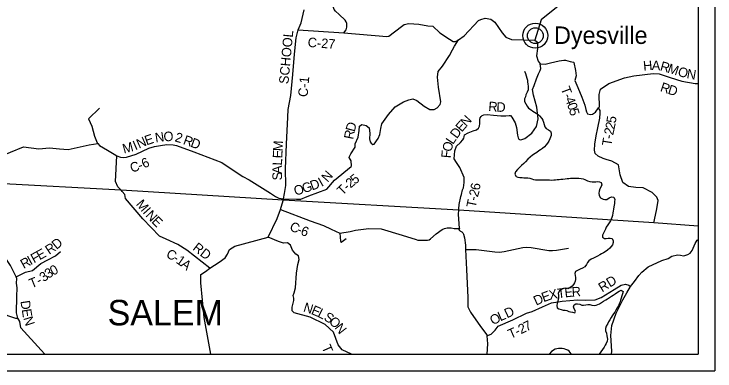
# Model space of a CAD drawing. Extents: x -84548 to 2262448, y -162180 to 525962.
# Drawn here: x -22558 to -515, y 130056 to 141282 of the extents above; entities that cross this region are included whole.
import ezdxf

# ---------------------------------------------------------------- set-up
doc = ezdxf.new("R2010")
doc.units = 0
for name, color, linetype in [('GM_X_Adjacent_County_Text', 7, 'Continuous'), ('GM_X_Corporation_Text', 7, 'Continuous'), ('GM_X_County', 7, 'Continuous'), ('GM_X_County_Road', 7, 'Continuous'), ('GM_X_Hydro', 7, 'Continuous'), ('GM_X_Interstate_Location', 7, 'Continuous'), ('GM_X_Major_River', 7, 'Continuous'), ('GM_X_Minor_Lake', 7, 'Continuous'), ('GM_X_Minor_River_Text', 7, 'Continuous'), ('GM_X_Township_Road', 7, 'Continuous'), ('GM_X_Township_Road_Text', 7, 'Continuous'), ('GM_X_Township_ROW', 7, 'Continuous')]:
    doc.layers.add(name, color=color, linetype=linetype)

msp = doc.modelspace()

# ---------------------------------------------------------------- linework, layer by layer
at = {"layer": 'GM_X_County'}
for p, q in [((-515, 167016), (-515, 130056)), ((-1043, 166488), (-1043, 130584)), ((-1043, 166488), (-1043, 130584)), ((-36947, 130584), (-1043, 130584)), ((-36947, 130584), (-1043, 130584)), ((-37475, 130056), (-515, 130056))]:
    msp.add_line(p, q, dxfattribs=at)
at = {"layer": 'GM_X_Hydro'}
for p, q in [((-19190, 135747), (-23639, 135977)), ((-14093, 135426), (-19190, 135747)), ((-8572, 135110), (-14093, 135426)), ((-2434, 134710), (-8572, 135110)), ((-1043, 134612), (-2434, 134710))]:
    msp.add_line(p, q, dxfattribs=at)
at = {"layer": 'GM_X_Interstate_Location'}
for points in [[(-6508, 139480), (-6475, 139408), (-6451, 139342), (-6431, 139270), (-6414, 139200), (-6406, 139142), (-6402, 139082), (-6392, 139004), (-6391, 138952), (-6393, 138896), (-6419, 138824), (-6458, 138739), (-6476, 138681), (-6502, 138617), (-6500, 138533), (-6465, 138453), (-6417, 138381), (-6375, 138321), (-6298, 138266), (-6238, 138232), (-6188, 138200), (-6134, 138162), (-6078, 138126), (-6028, 138081), (-5959, 137999), (-5923, 137939), (-5907, 137883), (-5886, 137803), (-5862, 137733), (-5824, 137681), (-5754, 137645), (-5691, 137600), (-5663, 137532), (-5669, 137463), (-5687, 137413), (-5708, 137353), (-5740, 137281), (-5784, 137221), (-5828, 137166), (-5875, 137100), (-5935, 137050), (-5999, 137007), (-6051, 136975), (-6116, 136931), (-6168, 136896), (-6248, 136844), (-6324, 136784), (-6400, 136715), (-6469, 136637), (-6525, 136582), (-6599, 136516), (-6662, 136450), (-6724, 136389), (-6792, 136323), (-6805, 136243), (-6769, 136173), (-6711, 136147), (-6655, 136143), (-6575, 136136), (-6521, 136134), (-6457, 136132), (-6405, 136128), (-6339, 136121), (-6275, 136101), (-6225, 136081), (-6155, 136070), (-6085, 136070), (-6031, 136068), (-5977, 136068), (-5917, 136067), (-5843, 136067), (-5783, 136063), (-5719, 136064), (-5659, 136062), (-5585, 136064), (-5533, 136068), (-5473, 136075), (-5419, 136081), (-5367, 136085), (-5299, 136089), (-5223, 136098), (-5165, 136106), (-5109, 136112), (-5055, 136117), (-4975, 136119), (-4869, 136119), (-4791, 136118), (-4727, 136110), (-4659, 136098), (-4603, 136081), (-4519, 136033), (-4445, 136015), (-4374, 136004), (-4310, 136004), (-4257, 136006), (-4195, 136010), (-4145, 136005), (-4092, 135985), (-4074, 135911), (-4098, 135853), (-4134, 135780)], [(-4134, 135780), (-4157, 135710), (-4167, 135652), (-4159, 135572), (-4110, 135498), (-4032, 135458), (-3980, 135447), (-3912, 135453), (-3842, 135497), (-3766, 135532), (-3696, 135526), (-3668, 135448), (-3670, 135388), (-3676, 135322), (-3681, 135272), (-3691, 135216), (-3701, 135148), (-3713, 135087), (-3724, 135029), (-3740, 134943), (-3758, 134883), (-3777, 134833), (-3805, 134775), (-3843, 134720), (-3885, 134652), (-3932, 134580), (-3962, 134512), (-3990, 134451), (-4023, 134393), (-4055, 134331), (-4049, 134259), (-3991, 134225), (-3937, 134227), (-3873, 134234), (-3811, 134236), (-3745, 134218), (-3714, 134148), (-3716, 134094), (-3742, 134024), (-3782, 133970), (-3825, 133918), (-3897, 133855), (-3969, 133805), (-4025, 133770), (-4081, 133742), (-4138, 133708), (-4210, 133669), (-4272, 133635), (-4336, 133607), (-4404, 133572), (-4478, 133520), (-4519, 133468), (-4559, 133402), (-4611, 133335), (-4676, 133287), (-4756, 133259), (-4822, 133226), (-4896, 133180), (-4918, 133118), (-4911, 133060), (-4901, 132998), (-4901, 132935), (-4909, 132877), (-4928, 132823), (-4962, 132771), (-5008, 132719), (-5084, 132672), (-5140, 132640), (-5208, 132658), (-5274, 132645), (-5342, 132621), (-5407, 132579), (-5443, 132508), (-5435, 132432), (-5436, 132356), (-5444, 132304), (-5458, 132248), (-5474, 132178), (-5485, 132112), (-5479, 132046), (-5421, 132012), (-5351, 131984), (-5287, 131973), (-5227, 131965), (-5173, 131955), (-5106, 131929), (-5054, 131918), (-4992, 131908), (-4922, 131880), (-4903, 131938), (-4943, 132008), (-4959, 132072), (-4947, 132138), (-4886, 132167), (-4834, 132169), (-4768, 132161), (-4697, 132129), (-4647, 132122), (-4579, 132134), (-4511, 132150), (-4447, 132145)], [(-4447, 132145), (-4385, 132121), (-4317, 132115), (-4251, 132125), (-4200, 132146), (-4148, 132172), (-4082, 132206), (-4024, 132247), (-3950, 132293), (-3898, 132327), (-3773, 132412), (-3721, 132444), (-3653, 132487), (-3581, 132533), (-3529, 132569), (-3464, 132598), (-3401, 132556), (-3423, 132484), (-3443, 132417), (-3466, 132347), (-3482, 132283), (-3500, 132233), (-3526, 132169), (-3553, 132101), (-3587, 132042), (-3631, 131970), (-3664, 131908), (-3702, 131854), (-3750, 131787), (-3780, 131735), (-3825, 131663), (-3859, 131601), (-3889, 131550), (-3935, 131464), (-3954, 131394), (-3954, 131314), (-3926, 131242), (-3911, 131162), (-3901, 131104), (-3897, 131054), (-3904, 130998), (-3934, 130919), (-3964, 130867), (-4000, 130801), (-4053, 130733), (-4103, 130662), (-4157, 130584), (-4157, 130584)]]:
    msp.add_lwpolyline(points, dxfattribs=at)
at = {"layer": 'GM_X_Major_River'}
for radius in [393, 249]:
    msp.add_circle((-6165, 140602), radius, dxfattribs=at)
at = {"layer": 'GM_X_Minor_Lake'}
for points in [[(-13411, 135512), (-13287, 135569), (-12725, 135775), (-12478, 136055), (-11954, 136488), (-11943, 136506), (-11959, 136665), (-12021, 136766), (-12023, 136780), (-11968, 136886), (-11828, 137092), (-11826, 137196), (-11733, 137413), (-11703, 137618), (-11692, 137758), (-11619, 137804), (-11487, 137780), (-11393, 137698), (-11371, 137520), (-11380, 137362), (-11361, 137264), (-11328, 137219), (-11276, 137176), (-11230, 137184), (-11103, 137372), (-11050, 137496), (-11026, 137682), (-10990, 137827), (-10784, 138125), (-10573, 138366), (-10314, 138519), (-10145, 138583), (-10014, 138615), (-9890, 138564), (-9659, 138385), (-9479, 138282), (-9347, 138282), (-9248, 138329), (-9159, 138435), (-9133, 138522), (-9213, 138977), (-9236, 139296), (-9218, 139472), (-9084, 139646), (-8862, 139981), (-8774, 140157), (-8701, 140276), (-8582, 140468)], [(-6176, 140455), (-6101, 140397), (-6094, 140198), (-6128, 139971), (-6080, 139797), (-6010, 139715), (-5855, 139700), (-5686, 139745), (-5411, 139814), (-5264, 139828), (-5217, 139829), (-5070, 139793), (-5069, 139793)], [(-5069, 139793), (-4967, 139768), (-4957, 139753), (-4899, 139503), (-4884, 139336), (-4918, 139194), (-4832, 138971), (-4698, 138670), (-4612, 138413), (-4574, 138276), (-4554, 138210), (-4537, 138165), (-4523, 138145), (-4427, 138120), (-4364, 138137), (-4272, 138191), (-4174, 138327), (-4147, 138364), (-4158, 138747), (-4114, 138915), (-3851, 139101), (-3358, 139272), (-3067, 139342), (-2456, 139411), (-2268, 139403), (-1928, 139290), (-1554, 139173), (-1141, 139093), (-1043, 139099)], [(-8490, 135602), (-8457, 135748), (-8424, 135817), (-8401, 135980), (-8402, 136140), (-8537, 136458), (-8646, 136616), (-8715, 136725), (-8695, 136977), (-8645, 137130), (-8519, 137244), (-8442, 137326), (-8411, 137375), (-8403, 137419), (-8390, 137485), (-8273, 137544), (-8114, 137606), (-8017, 137640), (-7948, 137697), (-7922, 137757), (-7909, 137837), (-7914, 137965), (-7904, 138022), (-7872, 138055), (-7831, 138095), (-7782, 138108), (-7677, 138118), (-7484, 138102), (-7245, 138083), (-7095, 138081), (-6988, 138095), (-6950, 138093), (-6900, 138034), (-6794, 137857), (-6755, 137718), (-6725, 137473), (-6702, 137391), (-6680, 137347), (-6664, 137338), (-6616, 137328), (-6491, 137368), (-6269, 137539), (-6124, 137742), (-6073, 137985), (-6116, 138350), (-6219, 138726), (-6257, 138907), (-6204, 139032), (-6125, 139247), (-6065, 139405), (-6010, 139501), (-5993, 139569), (-6010, 139715)], [(-20219, 137985), (-19873, 138321)], [(-4004, 136733), (-4029, 136742), (-4183, 136807), (-4278, 136891), (-4299, 137003), (-4291, 137194), (-4251, 137454), (-4194, 137700), (-4131, 138011), (-4121, 138165), (-4120, 138251), (-4174, 138327)], [(-23687, 136067), (-23688, 136069), (-23747, 136328), (-23755, 136415), (-23692, 136491), (-23452, 136613), (-22869, 136745), (-22790, 136882), (-22666, 136939), (-22260, 137101), (-21781, 137046), (-21437, 137078), (-21126, 137044), (-20859, 137025), (-20194, 137164), (-19924, 137208)], [(-8568, 135151), (-8555, 135293), (-8504, 135540), (-8490, 135602)], [(-14080, 135470), (-13674, 135455), (-13589, 135455), (-13535, 135462), (-13463, 135487), (-13411, 135512)], [(-21591, 130584), (-21705, 130712), (-22344, 131416), (-22376, 131611), (-22433, 131714), (-22481, 131889), (-22467, 132399), (-22464, 132666), (-22479, 132817), (-22473, 132969), (-22495, 133014), (-22669, 133371), (-23242, 134235), (-23385, 134405), (-23487, 134553), (-23516, 135246), (-23516, 135249)], [(-8553, 134541), (-8581, 134985), (-8572, 135110), (-8568, 135151)], [(-11950, 130584), (-12243, 130721), (-12369, 130883), (-12507, 131274), (-12774, 131516), (-13246, 131744), (-13748, 131885), (-13816, 131950), (-13807, 132062), (-13790, 132144), (-13756, 132268), (-13759, 132347), (-13780, 132431), (-13745, 132511), (-13709, 132671), (-13674, 133129), (-13636, 133401), (-13588, 133560), (-13615, 133674), (-13695, 133731), (-13796, 133853), (-13868, 134014), (-13954, 134084), (-14087, 134075), (-14243, 134123), (-14568, 134262)], [(-12317, 134385), (-12289, 134136), (-12284, 134117), (-12280, 134111), (-12275, 134108), (-12269, 134108), (-12261, 134112), (-12241, 134125), (-12114, 134221)], [(-22495, 133014), (-22193, 133161), (-21978, 133221), (-21716, 133431), (-21495, 133549), (-21251, 133678), (-21091, 133815)], [(-7688, 131164), (-7549, 131214), (-7425, 131334), (-7336, 131461), (-6874, 131659), (-6438, 131874), (-6262, 131924), (-5936, 132068), (-5653, 132204), (-5321, 132248), (-4841, 132298), (-4578, 132286), (-4286, 132292), (-4091, 132370), (-3690, 132619), (-3460, 132758), (-3333, 132784), (-3227, 132751), (-3171, 132712)], [(-26901, 131953), (-26395, 132177), (-25743, 132354), (-24553, 132256), (-23768, 132217), (-22768, 131796), (-22510, 131713), (-22433, 131714)], [(-5033, 130584), (-5037, 130593), (-5066, 130642), (-5100, 130679), (-5143, 130709), (-5200, 130733), (-5259, 130754), (-5317, 130767), (-5381, 130767), (-5440, 130764), (-5540, 130738), (-5651, 130672), (-5726, 130584)]]:
    msp.add_lwpolyline(points, dxfattribs=at)
at = {"layer": 'GM_X_Minor_River_Text'}
for points in [[(-5526, 142736), (-5525, 142728), (-5541, 142614), (-5546, 142563), (-5564, 142346), (-5507, 141959), (-5413, 141719), (-5382, 141651), (-5395, 141591), (-5403, 141577), (-5447, 141531), (-5978, 141095), (-6176, 140455)], [(-14096, 135415), (-14093, 135426), (-14080, 135470), (-14052, 135642), (-14013, 135893), (-14024, 136414), (-13989, 137191), (-13947, 138033), (-13934, 138278), (-13849, 138721), (-13790, 139383), (-13733, 140023), (-13681, 140535), (-13619, 140781), (-13531, 141003), (-13436, 141414)], [(-13619, 140781), (-12190, 140688), (-10831, 140571), (-10767, 140589), (-10375, 140888), (-10292, 140948), (-10139, 140979), (-9824, 140962), (-9547, 140912), (-9388, 140898), (-9167, 140689), (-8865, 140488), (-8749, 140419), (-8676, 140419), (-8610, 140447), (-8582, 140468), (-8405, 140599), (-7953, 141081), (-7873, 141108), (-7741, 141151), (-7566, 141121), (-7440, 141026), (-7212, 140692), (-7087, 140553), (-6918, 140481), (-6176, 140455)], [(-20219, 137985), (-20112, 137758), (-20026, 137444), (-19947, 137233), (-19924, 137208), (-19865, 137146), (-19621, 137000), (-19409, 136879), (-19329, 136820)], [(-19329, 136820), (-19213, 136781), (-19119, 136773), (-19022, 136784), (-18715, 136876), (-18316, 137059), (-18141, 137115), (-17956, 137151), (-17748, 137174), (-17555, 137172), (-17446, 137146), (-16906, 136948), (-16021, 136611), (-15694, 136390), (-15360, 136176), (-15166, 136068), (-14496, 135647), (-14330, 135538), (-14228, 135493), (-14080, 135470)], [(-19152, 135702), (-19190, 135747), (-19294, 135849), (-19369, 136014), (-19329, 136820)], [(-16400, 133291), (-17119, 133855), (-17408, 134037), (-17771, 134204), (-17979, 134296), (-18507, 134839), (-19055, 135482), (-19074, 135609), (-19152, 135702)], [(-16400, 133291), (-16103, 133482), (-15920, 133617), (-15843, 133725), (-15782, 133881), (-15617, 133982), (-14568, 134262), (-14287, 134849), (-14180, 135139), (-14096, 135415)], [(-14180, 135139), (-13246, 134781), (-12829, 134635), (-12585, 134517), (-12317, 134385), (-11989, 134447), (-11821, 134487), (-11399, 134533), (-11011, 134528), (-10352, 134332), (-9910, 134187), (-9855, 134175), (-9793, 134171), (-9553, 134171), (-9501, 134183), (-9461, 134210), (-9285, 134374), (-9095, 134503), (-9017, 134537), (-8941, 134557), (-8869, 134562), (-8810, 134559), (-8712, 134539), (-8553, 134541), (-8566, 134486), (-8480, 134437), (-8445, 134403), (-8421, 134363), (-8391, 134247), (-8365, 134013), (-8358, 133873), (-8330, 133246), (-8289, 132371), (-8282, 132074), (-8203, 131909), (-7884, 131456), (-7690, 131188), (-7688, 131164), (-7667, 130905), (-7688, 130584)], [(-3769, 130584), (-3753, 130682), (-3793, 131176), (-3759, 131487), (-3627, 131872), (-3413, 132289), (-3282, 132515), (-3171, 132712), (-3050, 132870), (-2906, 133063), (-2812, 133164), (-2618, 133330), (-2181, 133531), (-1986, 133595), (-1871, 133668), (-1688, 133710), (-1600, 133695), (-1507, 133682), (-1461, 133686), (-1367, 133721), (-1292, 133764), (-1237, 133846), (-1138, 134069), (-1073, 134167), (-1043, 134192)], [(-16365, 130584), (-16582, 131737), (-16678, 132827), (-16684, 133086), (-16539, 133183), (-16400, 133291)]]:
    msp.add_lwpolyline(points, dxfattribs=at)
at = {"layer": 'GM_X_Township_Road_Text'}
msp.add_lwpolyline([(-2434, 134710), (-2357, 135106), (-2308, 135348), (-2298, 135421), (-2340, 135520), (-2495, 135666), (-2776, 135816), (-3003, 135822), (-3231, 135853), (-3416, 135987), (-3492, 136226), (-3550, 136534), (-3761, 136653), (-3935, 136710), (-4004, 136733)], dxfattribs=at)
at = {"layer": 'GM_X_Township_ROW'}
for points in [[(-12190, 140688), (-12110, 140784), (-12090, 140870), (-12088, 140932), (-12094, 140988), (-12113, 141040), (-12146, 141084), (-12334, 141264), (-12450, 141376), (-12487, 141426), (-12509, 141487), (-12535, 141617)], [(-8358, 133873), (-8027, 133880), (-7434, 133803), (-7293, 133795), (-7146, 133812), (-6561, 133938), (-6438, 133951), (-6292, 133941), (-5735, 133849), (-5624, 133844), (-5496, 133855), (-5119, 133923)]]:
    msp.add_lwpolyline(points, dxfattribs=at)

# ---------------------------------------------------------------- texts
at = {"layer": 'GM_X_Adjacent_County_Text'}
msp.add_text('Dyesville', height=550, rotation=0, dxfattribs=at).set_placement((-5577, 140341))
at = {"layer": 'GM_X_Corporation_Text'}
msp.add_text('SALEM', height=800, rotation=0, dxfattribs=at).set_placement((-19615, 131491))
at = {"layer": 'GM_X_County_Road'}
for s, rotation, p in [('SCHOOL', 84.6809, (-13930, 139070)), ('C-27', 355.8896, (-13330, 140248)), ('C-1', 84.9702, (-13328, 138663)), ('N', 8.4382, (-18103, 137240)), ('O', 2.1024, (-17851, 137278)), ('2', 343.6472, (-17520, 137282)), ('N', 24.1603, (-18626, 137044)), ('E', 18.9703, (-18391, 137149)), ('R', 339.9159, (-17261, 137200)), ('D', 339.8656, (-17029, 137116)), ('M', 15.2362, (-19101, 136892)), ('I', 23.4091, (-18743, 136993)), ('M', 86.8115, (-14113, 136961)), ('E', 87.3978, (-14123, 136738)), ('6', 24.1155, (-18470, 136421)), ('L', 87.7709, (-14131, 136514)), ('C', 17.134, (-18858, 136291)), ('-', 20.3817, (-18605, 136370)), ('A', 89.6867, (-14133, 136253)), ('S', 91.2592, (-14128, 136053)), ('M', 310.1195, (-18740, 135293)), ('I', 311.3748, (-18526, 135039)), ('N', 313.2691, (-18437, 134938)), ('E', 314.6098, (-18251, 134741)), ('C', 338.4878, (-13915, 134484)), ('-', 338.6321, (-13685, 134393)), ('6', 339.4721, (-13566, 134347)), ('RD', 321.9517, (-16962, 133884)), ('C', 332.344, (-17800, 133646)), ('-', 328.0616, (-17587, 133534)), ('1', 324.6239, (-17486, 133472)), ('A', 322.4132, (-17338, 133366))]:
    msp.add_text(s, height=300, rotation=rotation, dxfattribs=at).set_placement(p)
at = {"layer": 'GM_X_Township_Road'}
for s, rotation, p in [('H', 5.5127, (-2759, 139496)), ('A', 357.8467, (-2506, 139521)), ('R', 344.1886, (-2261, 139514)), ('M', 342.2254, (-2027, 139447)), ('O', 344.1537, (-1706, 139345)), ('N', 349.8985, (-1420, 139265)), ('R', 341.1824, (-2260, 138861)), ('T', 290.9674, (-5373, 138939)), ('D', 342.9862, (-2017, 138779)), ('-', 293.4297, (-5287, 138716)), ('R', 355.2017, (-7651, 138233)), ('D', 357.1009, (-7395, 138212)), ('4', 292.244, (-5239, 138605)), ('0', 288.8315, (-5171, 138438)), ('5', 286.142, (-5112, 138267)), ('N', 47.6592, (-8333, 137719)), ('5', 81.217, (-3638, 137834)), ('D', 75.0484, (-11848, 137560)), ('E', 49.0854, (-8478, 137551)), ('2', 78.0808, (-3679, 137636)), ('R', 78.5783, (-11895, 137323)), ('D', 53.149, (-8633, 137344)), ('2', 78.0808, (-3717, 137455)), ('L', 56.7307, (-8753, 137160)), ('T', 80.8456, (-3776, 137116)), ('-', 79.2197, (-3740, 137335)), ('O', 74.8522, (-8812, 136928)), ('F', 85.2766, (-8826, 136741)), ('N', 48.655, (-12696, 135972)), ('5', 39.3978, (-11835, 135910)), ('D', 19.965, (-13185, 135730)), ('I', 29.2789, (-12889, 135842)), ('2', 39.7269, (-11977, 135792)), ('O', 16.5869, (-13708, 135567)), ('G', 18.0731, (-13446, 135645)), ('T', 44.9061, (-12224, 135558)), ('-', 40.962, (-12069, 135713)), ('6', 81.3159, (-7914, 135726)), ('2', 73.853, (-7974, 135507)), ('T', 78.3833, (-8043, 135173)), ('-', 77.9445, (-7998, 135392)), ('R', 33.6486, (-21453, 133703)), ('D', 39.5573, (-21221, 133860)), ('F', 28.7751, (-21931, 133437)), ('E', 28.7995, (-21754, 133535)), ('R', 28.7727, (-22255, 133260)), ('I', 28.7724, (-22039, 133378)), ('0', 28.9174, (-21328, 133048)), ('3', 38.3115, (-21618, 132842)), ('3', 32.274, (-21480, 132952)), ('T', 22.2351, (-22011, 132650)), ('-', 30.0698, (-21764, 132754)), ('RD', 31.799, (-4064, 132523)), ('R', 3.5108, (-5012, 132393)), ('E', 20.5957, (-5904, 132215)), ('X', 11.5192, (-5706, 132291)), ('T', 6.5972, (-5454, 132343)), ('E', 6.317, (-5231, 132368)), ('D', 278.9006, (-22358, 132250)), ('D', 24.8347, (-6138, 132107)), ('N', 342.3726, (-13482, 131933)), ('E', 336.7699, (-13237, 131856)), ('D', 24.9835, (-7053, 131708)), ('E', 278.9567, (-22317, 131988)), ('L', 333.9658, (-13035, 131769)), ('S', 328.7209, (-12839, 131674)), ('O', 30.1678, (-7488, 131486)), ('L', 23.2802, (-7268, 131615)), ('N', 288.0814, (-22270, 131717)), ('O', 318.5053, (-12678, 131577)), ('7', 26.5174, (-6445, 131292)), ('N', 307.8775, (-12490, 131413)), ('T', 23.4816, (-6945, 131063)), ('2', 25.8495, (-6615, 131210)), ('-', 24.9089, (-6731, 131156)), ('T', 293.6161, (-12889, 130805))]:
    msp.add_text(s, height=300, rotation=rotation, dxfattribs=at).set_placement(p)

doc.saveas('drawing.dxf')
